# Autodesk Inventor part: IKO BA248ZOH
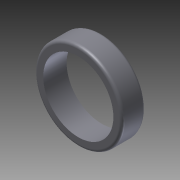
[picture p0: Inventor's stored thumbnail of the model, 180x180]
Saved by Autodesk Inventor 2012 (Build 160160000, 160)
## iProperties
Created: 2010-12
Part Number: IKO BA248ZOH
Document SubType Name: Modeling
Designer: Alex
Density: 7.85 g/cm^3
Material: Steel
Mass: 62.6831 g
Surface Area: 44.9675 cm^2
Volume: 7.9851 cm^3
Author: Alex
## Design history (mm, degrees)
sketch "Sketch1"
  geometry: C1 r 19.05 at (0, 0); C2 r 23.812 at (0, 0); 1 further point
  constraints: 2 centre point
  dimensions: "d2" = 38.1 diameter of C1; "d3" = 47.625 diameter of C2
extrude "Extrusion1" new body sketch "Sketch1" distance "d4" = 12.7; taper "d5" = 0 deg
fillet "Fillet1" dims "d6" = 1.5875
fillet "Fillet2" dims "d7" = 1.5875
body "Solid1"
